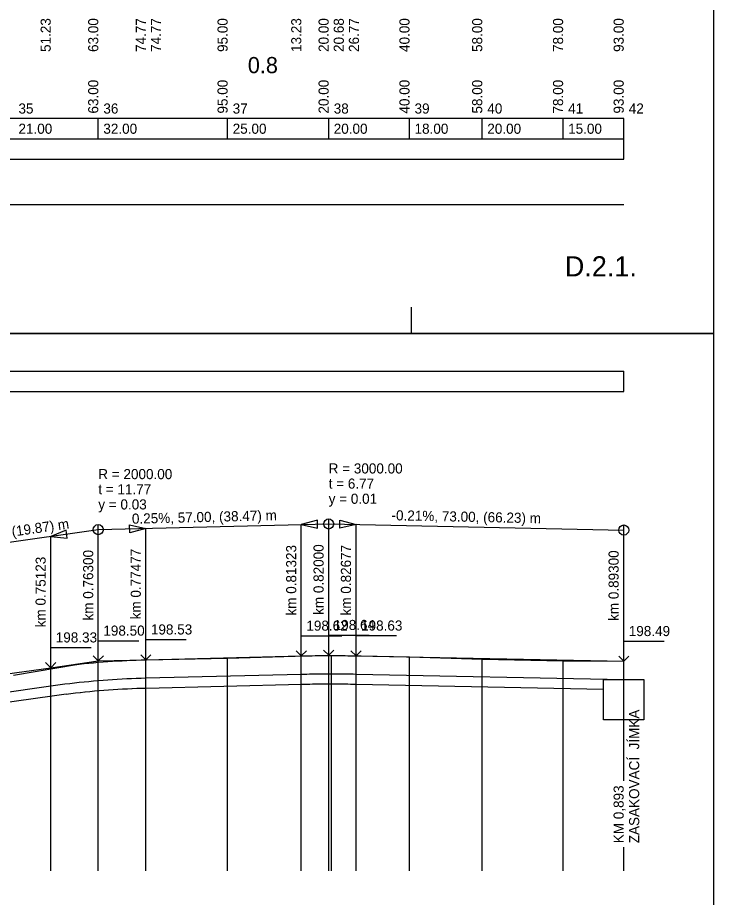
# Model space of a CAD drawing. Extents: x -51 to 53, y -74 to 15.
# Drawn here: x 35.86 to 53.08, y -28.51 to -6.73 of the extents above; entities that cross this region are included whole.
import ezdxf

# ---------------------------------------------------------------- set-up
doc = ezdxf.new("R2010")
doc.units = 0
for name, color, linetype in [('Implicitní', 7, 'Continuous'), ('KONSTRUKCE_L', 7, 'Continuous'), ('KOTY_L', 7, 'Continuous'), ('KOTY_S', 7, 'Continuous'), ('Nová vrstva (0)', 7, 'Continuous'), ('ROVINA_100', 7, 'Continuous'), ('SKLON_POMERY', 7, 'Continuous'), ('SMP_L', 7, 'Continuous'), ('TABULKY_L', 7, 'Continuous'), ('TABULKY_T', 7, 'Continuous'), ('TEREN_L', 7, 'Continuous'), ('V_POLYGON', 7, 'Continuous'), ('V_POLYGON_ZO', 7, 'Continuous')]:
    doc.layers.add(name, color=color, linetype=linetype)

msp = doc.modelspace()

# ---------------------------------------------------------------- linework, layer by layer
at = {"layer": 'Implicitní'}
msp.add_line((45.608, -14.546), (45.608, -13.897), dxfattribs=at)
for points in [[(-51.392, 15.154), (53.079, 15.154), (53.079, -14.546), (-51.392, -14.546)], [(-51.392, -14.546), (53.079, -14.546), (53.079, -44.246), (-51.392, -44.246)]]:
    msp.add_lwpolyline(points, close=True, dxfattribs=at)
at = {"layer": 'KONSTRUKCE_L'}
for p, q in [((38.566, -23.089), (38.684, -23.084)), ((38.684, -23.084), (38.801, -23.079)), ((38.801, -23.079), (38.919, -23.076)), ((38.919, -23.076), (39.037, -23.072)), ((39.037, -23.072), (42.883, -22.978)), ((42.883, -22.978), (42.951, -22.976)), ((42.951, -22.976), (43.019, -22.975)), ((43.019, -22.975), (43.086, -22.974)), ((43.086, -22.974), (43.154, -22.972)), ((43.154, -22.972), (43.222, -22.971)), ((43.222, -22.971), (43.289, -22.971)), ((43.289, -22.971), (43.357, -22.97)), ((43.357, -22.97), (43.425, -22.969)), ((43.425, -22.969), (43.492, -22.969)), ((43.492, -22.969), (43.56, -22.969)), ((43.56, -22.969), (43.628, -22.969)), ((43.628, -22.969), (43.695, -22.969)), ((43.695, -22.969), (43.763, -22.969)), ((43.763, -22.969), (43.831, -22.969)), ((43.831, -22.969), (43.898, -22.97)), ((43.898, -22.97), (43.966, -22.971)), ((43.966, -22.971), (44.034, -22.972)), ((44.034, -22.972), (44.101, -22.973)), ((44.101, -22.973), (44.169, -22.974)), ((44.169, -22.974), (44.237, -22.975)), ((44.237, -22.975), (50.86, -23.111)), ((34.697, -23.551), (36.683, -23.269)), ((36.683, -23.269), (36.801, -23.252)), ((36.801, -23.252), (36.919, -23.236)), ((36.919, -23.236), (37.036, -23.221)), ((37.036, -23.221), (37.154, -23.207)), ((37.154, -23.207), (37.272, -23.194)), ((37.272, -23.194), (37.389, -23.181)), ((37.389, -23.181), (37.507, -23.168)), ((37.507, -23.168), (37.625, -23.157)), ((37.625, -23.157), (37.742, -23.146)), ((37.742, -23.146), (37.86, -23.136)), ((37.86, -23.136), (37.978, -23.126)), ((37.978, -23.126), (38.095, -23.118)), ((38.095, -23.118), (38.213, -23.109)), ((38.213, -23.109), (38.331, -23.102)), ((38.331, -23.102), (38.448, -23.095)), ((38.448, -23.095), (38.566, -23.089))]:
    msp.add_line(p, q, dxfattribs=at)
at = {"layer": 'KOTY_L'}
for p, q in [((37.86, -27.851), (37.86, -22.651)), ((39.037, -27.851), (39.037, -22.625)), ((39.037, -27.851), (39.037, -22.625)), ((41.06, -27.851), (41.06, -22.581)), ((42.883, -27.851), (42.883, -22.53)), ((43.56, -27.851), (43.56, -22.511)), ((43.628, -27.851), (43.628, -22.513)), ((44.237, -27.851), (44.237, -22.525)), ((45.56, -27.851), (45.56, -22.551)), ((47.36, -27.851), (47.36, -22.611)), ((49.36, -27.851), (49.36, -22.651)), ((36.683, -27.851), (36.683, -22.847)), ((50.86, -25.619), (50.86, -22.661)), ((50.86, -27.851), (50.86, -27.264))]:
    msp.add_line(p, q, dxfattribs=at)
at = {"layer": 'Nová vrstva (0)'}
for p, q in [((39.043, -23.322), (42.889, -23.228)), ((42.889, -23.228), (42.957, -23.226)), ((42.956, -23.226), (43.024, -23.225)), ((43.023, -23.225), (43.091, -23.223)), ((43.091, -23.223), (43.158, -23.222)), ((43.158, -23.222), (43.225, -23.221)), ((43.225, -23.221), (43.292, -23.221)), ((43.292, -23.221), (43.359, -23.22)), ((43.359, -23.22), (43.427, -23.219)), ((43.426, -23.219), (43.494, -23.219)), ((43.493, -23.219), (43.561, -23.219)), ((43.56, -23.219), (43.628, -23.219)), ((43.627, -23.219), (43.695, -23.219)), ((43.694, -23.219), (43.762, -23.219)), ((43.762, -23.219), (43.829, -23.219)), ((43.829, -23.219), (43.896, -23.22)), ((43.896, -23.22), (43.963, -23.221)), ((43.963, -23.221), (44.03, -23.222)), ((44.03, -23.222), (44.098, -23.223)), ((44.097, -23.223), (44.165, -23.224)), ((44.164, -23.224), (44.232, -23.225)), ((44.232, -23.225), (50.36, -23.351)), ((34.732, -23.799), (36.719, -23.516)), ((36.718, -23.516), (36.836, -23.5)), ((36.834, -23.5), (36.952, -23.484)), ((36.95, -23.484), (37.068, -23.469)), ((37.067, -23.47), (37.184, -23.455)), ((37.183, -23.455), (37.3, -23.442)), ((37.299, -23.442), (37.417, -23.429)), ((37.415, -23.429), (37.533, -23.417)), ((37.531, -23.417), (37.649, -23.406)), ((37.648, -23.406), (37.765, -23.395)), ((37.764, -23.395), (37.882, -23.385)), ((37.88, -23.385), (37.998, -23.376)), ((37.996, -23.376), (38.114, -23.367)), ((38.112, -23.367), (38.23, -23.359)), ((38.229, -23.359), (38.346, -23.352)), ((38.345, -23.352), (38.463, -23.345)), ((38.461, -23.345), (38.579, -23.339)), ((38.577, -23.339), (38.695, -23.334)), ((38.693, -23.334), (38.811, -23.329)), ((38.81, -23.329), (38.927, -23.325)), ((38.926, -23.325), (39.043, -23.322))]:
    msp.add_line(p, q, dxfattribs=at)
msp.add_lwpolyline([(50.36, -23.111), (51.36, -23.111), (51.36, -24.111), (50.36, -24.111)], close=True, dxfattribs=at)
at = {"layer": 'SKLON_POMERY'}
for p, q in [((43.56, -19.261), (43.56, -19.136)), ((37.86, -19.401), (43.56, -19.261)), ((37.86, -19.401), (37.86, -19.276)), ((39.037, -22.622), (39.037, -19.372)), ((42.883, -22.528), (42.883, -19.278)), ((43.56, -22.511), (43.56, -19.261)), ((43.56, -19.261), (50.86, -19.411)), ((44.237, -22.525), (44.237, -19.275)), ((50.86, -19.411), (50.86, -19.286)), ((33.36, -20.041), (37.86, -19.401)), ((36.683, -22.819), (36.683, -19.569)), ((37.86, -22.651), (37.86, -19.401)), ((50.86, -22.661), (50.86, -19.411))]:
    msp.add_line(p, q, dxfattribs=at)
for points in [[(39.037, -19.372), (38.639, -19.482), (38.634, -19.282), (39.037, -19.372)], [(42.883, -19.278), (43.286, -19.368), (43.281, -19.168), (42.883, -19.278)], [(44.237, -19.275), (43.835, -19.367), (43.839, -19.167), (44.237, -19.275)], [(36.683, -19.569), (37.093, -19.611), (37.065, -19.413), (36.683, -19.569)]]:
    msp.add_lwpolyline(points, close=True, dxfattribs=at)
for points in [[(37.735, -22.526), (37.86, -22.651), (37.985, -22.526), (37.86, -22.651), (37.86, -22.151), (38.86, -22.151)], [(38.912, -22.497), (39.037, -22.622), (39.162, -22.497), (39.037, -22.622), (39.037, -22.122), (40.037, -22.122)], [(42.758, -22.403), (42.883, -22.528), (43.008, -22.403), (42.883, -22.528), (42.883, -22.028), (43.883, -22.028)], [(43.435, -22.386), (43.56, -22.511), (43.685, -22.386), (43.56, -22.511), (43.56, -22.011), (44.56, -22.011)], [(44.112, -22.4), (44.237, -22.525), (44.362, -22.4), (44.237, -22.525), (44.237, -22.025), (45.237, -22.025)], [(50.735, -22.536), (50.86, -22.661), (50.985, -22.536), (50.86, -22.661), (50.86, -22.161), (51.86, -22.161)], [(36.558, -22.694), (36.683, -22.819), (36.808, -22.694), (36.683, -22.819), (36.683, -22.319), (37.683, -22.319)]]:
    msp.add_lwpolyline(points, dxfattribs=at)
for centre in [(43.56, -19.261), (37.86, -19.401), (50.86, -19.411)]:
    msp.add_circle(centre, 0.125, dxfattribs=at)
at = {"layer": 'SMP_L'}
msp.add_line((24.26, -11.351), (50.86, -11.351), dxfattribs=at)
at = {"layer": 'TABULKY_L'}
for p, q in [((50.86, -9.226), (-38.44, -9.226)), ((37.86, -9.726), (37.86, -9.226)), ((41.06, -9.726), (41.06, -9.226)), ((43.56, -9.726), (43.56, -9.226)), ((45.56, -9.726), (45.56, -9.226)), ((47.36, -9.726), (47.36, -9.226)), ((49.36, -9.726), (49.36, -9.226)), ((50.86, -9.726), (50.86, -9.226)), ((50.86, -10.226), (50.86, -9.226)), ((-38.44, -9.726), (50.86, -9.726)), ((50.86, -10.226), (50.86, -9.726)), ((-38.44, -10.226), (50.86, -10.226)), ((-38.44, -15.482), (50.86, -15.482)), ((50.86, -15.982), (50.86, -15.482)), ((-38.44, -15.982), (50.86, -15.982))]:
    msp.add_line(p, q, dxfattribs=at)
at = {"layer": 'TEREN_L'}
for p, q in [((35.76, -23.001), (37.86, -22.651)), ((37.86, -22.651), (41.06, -22.581)), ((41.06, -22.581), (43.56, -22.511)), ((43.56, -22.511), (45.56, -22.551)), ((45.56, -22.551), (47.36, -22.611)), ((47.36, -22.611), (49.36, -22.651)), ((49.36, -22.651), (50.86, -22.661))]:
    msp.add_line(p, q, dxfattribs=at)
at = {"layer": 'V_POLYGON'}
for p, q in [((39.037, -22.622), (42.883, -22.528)), ((44.237, -22.525), (50.86, -22.661)), ((34.697, -23.101), (36.683, -22.819))]:
    msp.add_line(p, q, dxfattribs=at)
for points in [[(36.683, -22.819), (36.801, -22.802), (36.919, -22.786), (37.036, -22.771), (37.154, -22.757), (37.272, -22.744), (37.389, -22.731), (37.507, -22.718), (37.625, -22.707), (37.742, -22.696), (37.86, -22.686), (37.978, -22.676), (38.095, -22.668), (38.213, -22.659), (38.331, -22.652), (38.448, -22.645), (38.566, -22.639), (38.684, -22.634), (38.801, -22.629), (38.919, -22.626), (39.037, -22.622)], [(42.883, -22.528), (42.951, -22.526), (43.019, -22.525), (43.086, -22.524), (43.154, -22.522), (43.222, -22.521), (43.289, -22.521), (43.357, -22.52), (43.425, -22.519), (43.492, -22.519), (43.56, -22.519), (43.628, -22.519), (43.695, -22.519), (43.763, -22.519), (43.831, -22.519), (43.898, -22.52), (43.966, -22.521), (44.034, -22.522), (44.101, -22.523), (44.169, -22.524), (44.237, -22.525)]]:
    msp.add_lwpolyline(points, dxfattribs=at)
at = {"layer": 'V_POLYGON_ZO'}
for p, q in [((36.683, -22.819), (37.86, -22.651)), ((37.86, -22.651), (39.037, -22.622)), ((42.883, -22.528), (43.56, -22.511)), ((43.56, -22.511), (44.237, -22.525))]:
    msp.add_line(p, q, dxfattribs=at)

# ---------------------------------------------------------------- texts
at = {"layer": 'Implicitní'}
msp.add_text('D.2.1.', height=0.5, dxfattribs=at).set_placement((49.402, -13.133))
at = {"layer": 'KOTY_S'}
for s, p in [('51.23', (36.683, -7.576)), ('63.00', (37.86, -7.576)), ('74.77', (39.037, -7.576)), ('74.77', (39.412, -7.576)), ('95.00', (41.06, -7.576)), ('13.23', (42.883, -7.576)), ('20.00', (43.56, -7.576)), ('20.68', (43.935, -7.576)), ('26.77', (44.31, -7.576)), ('40.00', (45.56, -7.576)), ('58.00', (47.36, -7.576)), ('78.00', (49.36, -7.576)), ('93.00', (50.86, -7.576))]:
    msp.add_text(s, height=0.25, rotation=90, dxfattribs=at).set_placement(p)
at = {"layer": 'Nová vrstva (0)'}
for s, p in [('ZASAKOVACÍ  JÍMKA', (51.243, -27.164)), ('KM 0,893', (50.859, -27.164))]:
    msp.add_text(s, height=0.25, rotation=90, dxfattribs=at).set_placement(p)
at = {"layer": 'ROVINA_100'}
msp.add_text('0.8', height=0.4, dxfattribs=at).set_placement((41.56, -8.101))
at = {"layer": 'SKLON_POMERY'}
for s, p in [('R = 3000.00', (43.56, -18.011)), ('R = 2000.00', (37.86, -18.151)), ('t = 11.77', (37.86, -18.526)), ('t = 6.77', (43.56, -18.386)), ('y = 0.01', (43.56, -18.761)), ('y = 0.03', (37.86, -18.901)), ('198.50', (37.985, -22.026)), ('198.53', (39.162, -21.997)), ('198.62', (43.008, -21.903)), ('198.64', (43.685, -21.886)), ('198.63', (44.362, -21.9)), ('198.33', (36.808, -22.194)), ('198.49', (50.985, -22.036))]:
    msp.add_text(s, height=0.25, dxfattribs=at).set_placement(p)
for s, rotation, p in [('0.25%, 57.00, (38.47) m', 1.407, (38.695, -19.256)), ('-0.21%, 73.00, (66.23) m', 358.8229, (45.113, -19.168)), ('1.42%, 45.00, (19.87) m', 8.0945, (33.6, -19.878)), ('km 0.81323', 90, (42.758, -21.528)), ('km 0.82000', 90, (43.435, -21.511)), ('km 0.82677', 90, (44.112, -21.525)), ('km 0.76300', 90, (37.735, -21.651)), ('km 0.77477', 90, (38.912, -21.622)), ('km 0.89300', 90, (50.735, -21.661)), ('km 0.75123', 90, (36.558, -21.819))]:
    msp.add_text(s, height=0.25, rotation=rotation, dxfattribs=at).set_placement(p)
at = {"layer": 'TABULKY_T'}
for s, p in [('63.00', (37.86, -9.101)), ('95.00', (41.06, -9.101)), ('20.00', (43.56, -9.101)), ('40.00', (45.56, -9.101)), ('58.00', (47.36, -9.101)), ('78.00', (49.36, -9.101)), ('93.00', (50.86, -9.101))]:
    msp.add_text(s, height=0.25, rotation=90, dxfattribs=at).set_placement(p)
for s, p in [('35', (35.885, -9.101)), ('36', (37.985, -9.101)), ('37', (41.185, -9.101)), ('38', (43.685, -9.101)), ('39', (45.685, -9.101)), ('40', (47.485, -9.101)), ('41', (49.485, -9.101)), ('42', (50.985, -9.101)), ('21.00', (35.885, -9.601)), ('32.00', (37.985, -9.601)), ('25.00', (41.185, -9.601)), ('20.00', (43.685, -9.601)), ('18.00', (45.685, -9.601)), ('20.00', (47.485, -9.601)), ('15.00', (49.485, -9.601))]:
    msp.add_text(s, height=0.25, dxfattribs=at).set_placement(p)

doc.saveas('drawing.dxf')
